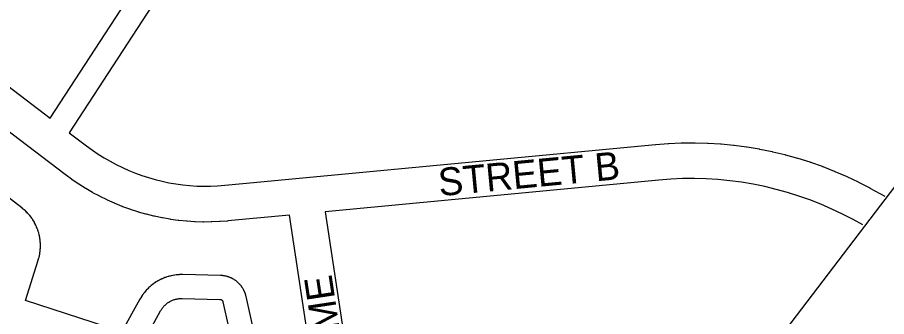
# Model space of a CAD drawing. Extents: x 599744 to 600217, y 4827560 to 4828065.
# Drawn here: x 600025.18 to 600047.03, y 4827990.19 to 4827997.7 of the extents above; entities that cross this region are included whole.
import ezdxf

# ---------------------------------------------------------------- set-up
doc = ezdxf.new("R2010")
doc.units = 0
doc.layers.add('G-ANNO-KEYP', color=7, linetype='Continuous')
doc.layers.add('G-TTLB-OTLN', color=7, linetype='Continuous')

msp = doc.modelspace()

# ---------------------------------------------------------------- linework, layer by layer
at = {"layer": 'G-ANNO-KEYP'}
for points in [[(600026.008, 4827995.17), (600028.908, 4827999.634)], [(600029.411, 4827999.31), (600026.486, 4827994.807)], [(600023.868, 4827996.798), (600026.008, 4827995.17)], [(600034.437, 4827976.79), (600032.018, 4827992.737), (600030.473, 4827992.591), (600030.473, 4827992.591), (600030.465, 4827992.59), (600030.274, 4827992.575), (600030.273, 4827992.575), (600030.258, 4827992.574), (600030.067, 4827992.566), (600030.065, 4827992.567), (600030.051, 4827992.566), (600029.859, 4827992.565), (600029.857, 4827992.566), (600029.843, 4827992.565), (600029.652, 4827992.571), (600029.649, 4827992.572), (600029.636, 4827992.571), (600029.445, 4827992.584), (600029.441, 4827992.585), (600029.429, 4827992.585), (600029.238, 4827992.604), (600029.234, 4827992.606), (600029.222, 4827992.606), (600029.033, 4827992.632), (600029.027, 4827992.634), (600029.017, 4827992.635), (600028.828, 4827992.667), (600028.822, 4827992.67), (600028.813, 4827992.67), (600028.625, 4827992.71), (600028.619, 4827992.713), (600028.609, 4827992.713), (600028.424, 4827992.759), (600028.416, 4827992.763), (600028.408, 4827992.763), (600028.224, 4827992.816), (600028.216, 4827992.82), (600028.209, 4827992.821), (600028.026, 4827992.88), (600028.018, 4827992.884), (600028.011, 4827992.885), (600027.831, 4827992.95), (600027.822, 4827992.955), (600027.816, 4827992.956), (600027.639, 4827993.028), (600027.629, 4827993.033), (600027.624, 4827993.034), (600027.449, 4827993.112), (600027.439, 4827993.118), (600027.435, 4827993.119), (600027.263, 4827993.203), (600027.252, 4827993.21), (600027.249, 4827993.21), (600027.08, 4827993.301), (600027.069, 4827993.308), (600027.066, 4827993.308), (600026.9, 4827993.405), (600026.889, 4827993.412), (600026.886, 4827993.413), (600026.724, 4827993.515), (600026.712, 4827993.523), (600026.711, 4827993.524), (600026.553, 4827993.631), (600026.54, 4827993.64), (600026.54, 4827993.64), (600026.385, 4827993.754), (600026.379, 4827993.758), (600026.379, 4827993.759), (600023.327, 4827996.08)], [(600025.524, 4827992.685), (600025.519, 4827992.69), (600025.518, 4827992.693), (600025.499, 4827992.717), (600025.494, 4827992.722), (600025.493, 4827992.725), (600025.473, 4827992.748), (600025.468, 4827992.754), (600025.467, 4827992.756), (600025.446, 4827992.779), (600025.44, 4827992.785), (600025.439, 4827992.786), (600025.418, 4827992.809), (600025.412, 4827992.814), (600025.411, 4827992.816), (600025.389, 4827992.837), (600025.382, 4827992.843), (600025.382, 4827992.844), (600025.359, 4827992.865), (600025.352, 4827992.871), (600025.352, 4827992.872), (600025.328, 4827992.891), (600025.321, 4827992.898), (600025.321, 4827992.898), (600025.297, 4827992.917), (600025.294, 4827992.919), (600025.293, 4827992.92), (600021.868, 4827995.556)], [(600026.486, 4827994.807), (600026.921, 4827994.476), (600027.065, 4827994.371), (600027.21, 4827994.272), (600027.359, 4827994.178), (600027.511, 4827994.09), (600027.665, 4827994.007), (600027.823, 4827993.93), (600027.983, 4827993.859), (600028.146, 4827993.793), (600028.311, 4827993.733), (600028.478, 4827993.679), (600028.647, 4827993.63), (600028.818, 4827993.588), (600028.989, 4827993.552), (600029.163, 4827993.522), (600029.336, 4827993.498), (600029.511, 4827993.481), (600029.687, 4827993.469), (600029.862, 4827993.464), (600030.038, 4827993.465), (600030.213, 4827993.472)], [(600030.213, 4827993.472), (600030.392, 4827993.486), (600030.847, 4827993.529), (600030.847, 4827993.529), (600032.357, 4827993.673), (600041.221, 4827994.514), (600041.222, 4827994.513), (600041.229, 4827994.514), (600041.541, 4827994.538), (600041.542, 4827994.538), (600041.556, 4827994.539), (600041.868, 4827994.552), (600041.87, 4827994.552), (600041.884, 4827994.553), (600042.197, 4827994.555), (600042.199, 4827994.555), (600042.212, 4827994.555), (600042.525, 4827994.547), (600042.528, 4827994.546), (600042.54, 4827994.546), (600042.852, 4827994.527), (600042.856, 4827994.525), (600042.868, 4827994.526), (600043.179, 4827994.495), (600043.183, 4827994.494), (600043.194, 4827994.494), (600043.504, 4827994.453), (600043.509, 4827994.451), (600043.52, 4827994.451), (600043.828, 4827994.399), (600043.833, 4827994.396), (600043.843, 4827994.396), (600044.149, 4827994.334), (600044.156, 4827994.331), (600044.165, 4827994.33), (600044.468, 4827994.258), (600044.475, 4827994.254), (600044.484, 4827994.254), (600044.785, 4827994.17), (600044.792, 4827994.167), (600044.8, 4827994.166), (600045.098, 4827994.072), (600045.106, 4827994.068), (600045.113, 4827994.067), (600045.407, 4827993.963), (600045.416, 4827993.958), (600045.422, 4827993.958), (600045.713, 4827993.843), (600045.722, 4827993.838), (600045.727, 4827993.837), (600046.014, 4827993.713), (600046.024, 4827993.708), (600046.028, 4827993.707), (600046.311, 4827993.573), (600046.321, 4827993.566), (600046.325, 4827993.566), (600046.602, 4827993.422), (600046.607, 4827993.418), (600046.609, 4827993.418), (600046.982, 4827993.216)], [(600045.377, 4827993.009), (600045.1, 4827993.118), (600044.82, 4827993.217), (600044.538, 4827993.306), (600044.251, 4827993.385), (600043.963, 4827993.454), (600043.671, 4827993.513), (600043.379, 4827993.562), (600043.085, 4827993.601), (600042.789, 4827993.63), (600042.493, 4827993.648), (600042.196, 4827993.656), (600041.899, 4827993.654), (600041.603, 4827993.641), (600041.302, 4827993.618), (600032.915, 4827992.822), (600035.198, 4827977.77)], [(600046.43, 4827992.493), (600046.184, 4827992.625), (600045.918, 4827992.764), (600045.649, 4827992.891), (600045.377, 4827993.009)], [(600025.757, 4827992.053), (600025.755, 4827992.084), (600025.754, 4827992.094), (600025.754, 4827992.094), (600025.75, 4827992.124), (600025.75, 4827992.127), (600025.749, 4827992.134), (600025.744, 4827992.165), (600025.744, 4827992.165), (600025.743, 4827992.175), (600025.737, 4827992.205), (600025.737, 4827992.205), (600025.735, 4827992.215), (600025.728, 4827992.245), (600025.728, 4827992.246), (600025.726, 4827992.254), (600025.718, 4827992.284), (600025.717, 4827992.285), (600025.716, 4827992.294), (600025.707, 4827992.323), (600025.706, 4827992.325), (600025.704, 4827992.333), (600025.694, 4827992.362), (600025.693, 4827992.364), (600025.691, 4827992.371), (600025.68, 4827992.4), (600025.679, 4827992.403), (600025.677, 4827992.41), (600025.665, 4827992.438), (600025.663, 4827992.441), (600025.661, 4827992.447), (600025.649, 4827992.475), (600025.646, 4827992.478), (600025.644, 4827992.484), (600025.631, 4827992.512), (600025.628, 4827992.515), (600025.626, 4827992.521), (600025.612, 4827992.548), (600025.609, 4827992.552), (600025.607, 4827992.557), (600025.592, 4827992.583), (600025.588, 4827992.587), (600025.586, 4827992.592), (600025.57, 4827992.618), (600025.566, 4827992.622), (600025.565, 4827992.626), (600025.548, 4827992.652), (600025.543, 4827992.656), (600025.542, 4827992.66), (600025.524, 4827992.685)], [(600027.419, 4827989.932), (600025.382, 4827990.593), (600025.704, 4827991.606), (600025.704, 4827991.608), (600025.705, 4827991.611), (600025.714, 4827991.64), (600025.715, 4827991.645), (600025.717, 4827991.65), (600025.725, 4827991.68), (600025.725, 4827991.685), (600025.727, 4827991.689), (600025.734, 4827991.719), (600025.734, 4827991.725), (600025.736, 4827991.729), (600025.742, 4827991.759), (600025.742, 4827991.766), (600025.743, 4827991.769), (600025.748, 4827991.799), (600025.748, 4827991.806), (600025.75, 4827991.81), (600025.753, 4827991.84), (600025.753, 4827991.847), (600025.754, 4827991.85), (600025.757, 4827991.88), (600025.757, 4827991.888), (600025.758, 4827991.891), (600025.759, 4827991.921), (600025.759, 4827991.929), (600025.76, 4827991.931), (600025.76, 4827991.962), (600025.76, 4827991.971), (600025.76, 4827991.972), (600025.76, 4827992.003), (600025.759, 4827992.012), (600025.76, 4827992.013), (600025.758, 4827992.043), (600025.757, 4827992.053), (600025.757, 4827992.053)], [(600029.3, 4827991.244), (600029.291, 4827991.243), (600029.29, 4827991.244), (600029.259, 4827991.243), (600029.25, 4827991.242), (600029.249, 4827991.242), (600029.219, 4827991.24), (600029.209, 4827991.239), (600029.208, 4827991.24), (600029.178, 4827991.237), (600029.169, 4827991.236), (600029.168, 4827991.235), (600029.139, 4827991.232), (600029.139, 4827991.232), (600029.139, 4827991.232), (600029.137, 4827991.231), (600029.137, 4827991.231), (600029.127, 4827991.23), (600029.097, 4827991.225), (600029.096, 4827991.225), (600029.087, 4827991.223), (600029.057, 4827991.217), (600029.056, 4827991.217), (600029.047, 4827991.215), (600029.017, 4827991.208), (600029.016, 4827991.207), (600029.007, 4827991.205), (600028.977, 4827991.197), (600028.976, 4827991.196), (600028.968, 4827991.194), (600028.939, 4827991.185), (600028.936, 4827991.184), (600028.929, 4827991.182), (600028.9, 4827991.172), (600028.897, 4827991.17), (600028.89, 4827991.169), (600028.862, 4827991.158), (600028.859, 4827991.156), (600028.852, 4827991.154), (600028.824, 4827991.142), (600028.821, 4827991.139), (600028.815, 4827991.138), (600028.787, 4827991.125), (600028.784, 4827991.122), (600028.778, 4827991.12), (600028.75, 4827991.106), (600028.747, 4827991.103), (600028.741, 4827991.101), (600028.714, 4827991.087), (600028.711, 4827991.083), (600028.706, 4827991.082), (600028.679, 4827991.066)], [(600030.627, 4827991.12), (600030.615, 4827991.127), (600030.614, 4827991.128), (600030.606, 4827991.133), (600030.594, 4827991.139), (600030.592, 4827991.14), (600030.585, 4827991.144), (600030.573, 4827991.15), (600030.57, 4827991.151), (600030.563, 4827991.155), (600030.551, 4827991.161), (600030.548, 4827991.161), (600030.541, 4827991.165), (600030.529, 4827991.171), (600030.525, 4827991.171), (600030.519, 4827991.174), (600030.506, 4827991.179), (600030.502, 4827991.18), (600030.496, 4827991.183), (600030.483, 4827991.187), (600030.479, 4827991.188), (600030.473, 4827991.191), (600030.46, 4827991.194), (600030.455, 4827991.195), (600030.45, 4827991.197), (600030.437, 4827991.201), (600030.431, 4827991.201), (600030.427, 4827991.203), (600030.413, 4827991.206), (600030.407, 4827991.207), (600030.403, 4827991.208), (600030.389, 4827991.211), (600030.382, 4827991.211), (600030.379, 4827991.213), (600030.365, 4827991.215), (600030.358, 4827991.215), (600030.355, 4827991.216), (600030.342, 4827991.218), (600030.334, 4827991.218), (600030.331, 4827991.219), (600030.317, 4827991.22), (600030.309, 4827991.22), (600030.307, 4827991.22), (600030.293, 4827991.221), (600030.289, 4827991.221), (600030.288, 4827991.221), (600029.336, 4827991.243), (600029.332, 4827991.243), (600029.331, 4827991.243), (600029.3, 4827991.244)], [(600028.679, 4827991.066), (600028.675, 4827991.062), (600028.671, 4827991.06), (600028.645, 4827991.044), (600028.64, 4827991.04), (600028.636, 4827991.038), (600028.611, 4827991.021), (600028.606, 4827991.016), (600028.603, 4827991.015), (600028.578, 4827990.996), (600028.573, 4827990.991), (600028.57, 4827990.99), (600028.546, 4827990.971), (600028.541, 4827990.966), (600028.539, 4827990.964), (600028.515, 4827990.945), (600028.51, 4827990.939), (600028.508, 4827990.938), (600028.485, 4827990.917), (600028.479, 4827990.911), (600028.478, 4827990.91), (600028.456, 4827990.888), (600028.45, 4827990.882), (600028.449, 4827990.881), (600028.428, 4827990.859), (600028.421, 4827990.852), (600028.421, 4827990.851), (600028.4, 4827990.828), (600028.394, 4827990.821), (600028.394, 4827990.821), (600028.374, 4827990.797), (600028.369, 4827990.79), (600028.368, 4827990.789), (600028.35, 4827990.766), (600028.35, 4827990.766), (600028.35, 4827990.766), (600028.349, 4827990.765), (600028.349, 4827990.765), (600028.343, 4827990.757), (600028.325, 4827990.732), (600028.325, 4827990.731), (600028.319, 4827990.723), (600028.302, 4827990.698), (600028.302, 4827990.697), (600028.297, 4827990.689), (600028.281, 4827990.663), (600028.28, 4827990.662), (600028.275, 4827990.655), (600028.26, 4827990.628), (600028.26, 4827990.627)], [(600030.892, 4827990.813), (600030.886, 4827990.826), (600030.884, 4827990.829), (600030.882, 4827990.835), (600030.876, 4827990.847), (600030.873, 4827990.851), (600030.871, 4827990.857), (600030.865, 4827990.869), (600030.861, 4827990.873), (600030.859, 4827990.878), (600030.853, 4827990.89), (600030.849, 4827990.894), (600030.847, 4827990.899), (600030.84, 4827990.911), (600030.836, 4827990.915), (600030.834, 4827990.92), (600030.826, 4827990.931), (600030.822, 4827990.936), (600030.82, 4827990.939), (600030.812, 4827990.95), (600030.807, 4827990.956), (600030.806, 4827990.959), (600030.797, 4827990.97), (600030.792, 4827990.975), (600030.791, 4827990.978), (600030.782, 4827990.988), (600030.776, 4827990.994), (600030.775, 4827990.996), (600030.766, 4827991.006), (600030.759, 4827991.012), (600030.758, 4827991.014), (600030.749, 4827991.024), (600030.742, 4827991.03), (600030.741, 4827991.031), (600030.732, 4827991.04), (600030.724, 4827991.047), (600030.724, 4827991.048), (600030.714, 4827991.056), (600030.705, 4827991.063), (600030.705, 4827991.064), (600030.695, 4827991.072), (600030.689, 4827991.077), (600030.687, 4827991.079), (600030.676, 4827991.087), (600030.676, 4827991.087), (600030.667, 4827991.093), (600030.656, 4827991.101), (600030.655, 4827991.101), (600030.647, 4827991.107), (600030.636, 4827991.114), (600030.635, 4827991.115), (600030.627, 4827991.12)], [(600031.497, 4827988.14), (600030.93, 4827990.693), (600030.93, 4827990.694), (600030.929, 4827990.698), (600030.926, 4827990.711), (600030.925, 4827990.713), (600030.923, 4827990.722), (600030.92, 4827990.735), (600030.919, 4827990.737), (600030.917, 4827990.745), (600030.913, 4827990.758), (600030.911, 4827990.76), (600030.909, 4827990.768), (600030.905, 4827990.781), (600030.903, 4827990.783), (600030.901, 4827990.791), (600030.896, 4827990.803), (600030.894, 4827990.806), (600030.892, 4827990.813)], [(600028.26, 4827990.627), (600028.258, 4827990.624), (600027.793, 4827989.782)], [(600028.305, 4827989.469), (600028.781, 4827990.332), (600028.792, 4827990.352), (600028.803, 4827990.369), (600028.814, 4827990.387), (600028.826, 4827990.403), (600028.839, 4827990.419), (600028.852, 4827990.435), (600028.865, 4827990.45), (600028.879, 4827990.465), (600028.894, 4827990.48), (600028.909, 4827990.493)], [(600028.909, 4827990.493), (600028.925, 4827990.507), (600028.941, 4827990.52), (600028.957, 4827990.532), (600028.974, 4827990.543), (600028.991, 4827990.554), (600029.009, 4827990.565), (600029.026, 4827990.575), (600029.045, 4827990.584), (600029.063, 4827990.593), (600029.082, 4827990.601), (600029.101, 4827990.608), (600029.12, 4827990.615), (600029.14, 4827990.621), (600029.159, 4827990.626), (600029.18, 4827990.631), (600029.199, 4827990.635), (600029.22, 4827990.638), (600029.24, 4827990.641), (600029.261, 4827990.643), (600029.281, 4827990.644), (600029.302, 4827990.645), (600029.325, 4827990.645), (600030.271, 4827990.623), (600030.276, 4827990.622), (600030.279, 4827990.622), (600030.282, 4827990.622), (600030.285, 4827990.621), (600030.287, 4827990.621), (600030.29, 4827990.62), (600030.293, 4827990.62), (600030.295, 4827990.619), (600030.298, 4827990.618), (600030.3, 4827990.617), (600030.303, 4827990.616), (600030.305, 4827990.615), (600030.308, 4827990.613), (600030.31, 4827990.612), (600030.312, 4827990.611), (600030.315, 4827990.609), (600030.317, 4827990.608), (600030.319, 4827990.606), (600030.321, 4827990.604), (600030.323, 4827990.603), (600030.325, 4827990.601), (600030.327, 4827990.599), (600030.329, 4827990.597), (600030.331, 4827990.595), (600030.332, 4827990.593), (600030.334, 4827990.59), (600030.335, 4827990.588), (600030.337, 4827990.586), (600030.338, 4827990.583), (600030.339, 4827990.581), (600030.341, 4827990.579), (600030.342, 4827990.576), (600030.343, 4827990.573), (600030.344, 4827990.571), (600030.344, 4827990.569), (600030.345, 4827990.566), (600030.346, 4827990.561), (600030.912, 4827988.013)]]:
    msp.add_lwpolyline(points, dxfattribs=at)
at = {"layer": 'G-TTLB-OTLN'}
msp.add_lwpolyline([(599983.747, 4827984.522), (600022.202, 4828034.93), (600058.02, 4828007.605), (600019.565, 4827957.197)], close=True, dxfattribs=at)

# ---------------------------------------------------------------- texts
at = {"layer": 'G-ANNO-KEYP'}
for s, rotation, p in [('STREET B', 5.4187, (600035.792, 4827993.212)), ('STREET NAME', 98.6234, (600034.072, 4827984.683))]:
    msp.add_text(s, height=0.7, rotation=rotation, dxfattribs=at).set_placement(p)

doc.saveas('drawing.dxf')
